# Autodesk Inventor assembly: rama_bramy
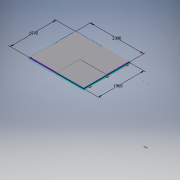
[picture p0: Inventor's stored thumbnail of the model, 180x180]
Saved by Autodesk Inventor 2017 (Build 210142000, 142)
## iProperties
Created: 2020-09
Part Number: rama_bramy
Document SubType Name: Konstrukcja spawana
Designer: X
Weld Material: Stal miękka, spawana
Mass: 112959 g
Surface Area: 245230 cm^2
Volume: 32532.3 cm^3
Density: 3.47219 g/cm^3
_SolveAssemblyDoc: Frame Generator Solve Assembly
_Version: 15.0.0
Author: X
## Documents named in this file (9)
- C:\Users\WindowsX\Desktop\brama\rama_bramy.iam
- C:\Users\WindowsX\Desktop\brama\rama bramy.ipt
- C:\Users\WindowsX\Desktop\brama\rama_bramy\Frame\Frame0001.iam
- C:\Users\WindowsX\Desktop\brama\skrzydlo_lewe.iam
- C:\Users\WindowsX\Desktop\brama\zawias_100_30.iam
- C:\Users\WindowsX\Desktop\brama\blacha_p_g.ipt
- C:\Users\WindowsX\Desktop\brama\blacha_l_g.ipt
- C:\Users\WindowsX\Desktop\brama\blacha_wew_a.ipt
- C:\Users\WindowsX\Desktop\brama\tulejka.ipt
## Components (26 placed, 8 different names)
1. rama bramy:1 — Zestawiający:3
2. Frame0001:1 [sub-assembly] — Zestawiający:1, Zestawiający:2, Zestawiający:4, Zestawiający:5, Zestawiający:6, Zestawiający:7, Zestawiający:8, Zestawiający:9, Równoległy:1, Zestawiający:10, Równoległy:3, Kąt:1, Kąt:2
3. skrzydlo_lewe:1 [sub-assembly] — Równoległy:2, Zestawiający:14, Zestawiający:15, Kąt:2, Zestawiający:19
4. skrzydlo_lewe:2 [sub-assembly] — Zestawiający:1, Zestawiający:2, Zestawiający:3, Zestawiający:16, Zestawiający:17
5. zawias_100_30:1 [sub-assembly] — Zestawiający:4, Równoległy:1, Zestawiający:10, Równoległy:2, Zestawiający:12
6. zawias_100_30:2 [sub-assembly] — Zestawiający:5
7. zawias_100_30:3 [sub-assembly] — Zestawiający:6
8. zawias_100_30:4 [sub-assembly] — Zestawiający:7
9. zawias_100_30:5 [sub-assembly] — Zestawiający:8
10. zawias_100_30:6 [sub-assembly] — Zestawiający:9
11. blacha_p_g:1 — Zestawiający:17, Zestawiający:18
12. blacha_p_g:2 — Zestawiający:16, Zestawiający:18
13. blacha_l_g:1
14. blacha_l_g:2 — Zestawiający:19
15. blacha_wew_a:1
16. blacha_wew_a:2
17. blacha_wew_a:3
18. blacha_wew_a:4
19. tulejka:1
20. tulejka:2
21. tulejka:3
22. tulejka:4
23. tulejka:5
24. tulejka:6
25. tulejka:7
26. tulejka:8
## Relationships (22: Mate 17, Flush 3, Angle 2)
- Zestawiający:1 [Mate]: Frame0001:1 ↔ skrzydlo_lewe:2
- Zestawiający:2 [Mate]: Frame0001:1 ↔ skrzydlo_lewe:2
- Zestawiający:3 [Mate]: rama bramy:1 ↔ skrzydlo_lewe:2
- Zestawiający:4 [Mate]: Frame0001:1 ↔ zawias_100_30:1
- Zestawiający:5 [Mate]: Frame0001:1 ↔ zawias_100_30:2
- Zestawiający:6 [Mate]: Frame0001:1 ↔ zawias_100_30:3
- Zestawiający:7 [Mate]: Frame0001:1 ↔ zawias_100_30:4
- Zestawiający:8 [Mate]: Frame0001:1 ↔ zawias_100_30:5
- Zestawiający:9 [Mate]: Frame0001:1 ↔ zawias_100_30:6
- Równoległy:1 [Flush]: Frame0001:1 ↔ zawias_100_30:1
- Zestawiający:10 [Mate]: Frame0001:1 ↔ zawias_100_30:1
- Równoległy:2 [Flush]: skrzydlo_lewe:1 ↔ zawias_100_30:1
- Równoległy:3 [Flush]: Frame0001:1
- Zestawiający:12 [Mate]: zawias_100_30:1
- Kąt:1 [Angle]: Frame0001:1
- Zestawiający:14 [Mate]: skrzydlo_lewe:1
- Zestawiający:15 [Mate]: skrzydlo_lewe:1
- Kąt:2 [Angle]: Frame0001:1 ↔ skrzydlo_lewe:1
- Zestawiający:16 [Mate]: skrzydlo_lewe:2 ↔ blacha_p_g:2
- Zestawiający:17 [Mate]: skrzydlo_lewe:2 ↔ blacha_p_g:1
- Zestawiający:18 [Mate]: blacha_p_g:1 ↔ blacha_p_g:2
- Zestawiający:19 [Mate]: skrzydlo_lewe:1 ↔ blacha_l_g:2
